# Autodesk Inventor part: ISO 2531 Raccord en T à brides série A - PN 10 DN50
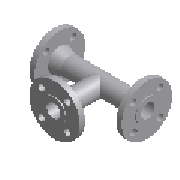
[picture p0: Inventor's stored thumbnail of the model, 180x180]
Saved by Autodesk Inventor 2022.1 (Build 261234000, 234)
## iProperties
Created: 2021-02
Part Number: ISO 2531 Raccord en T à brides série A - PN 10 DN50
Material: Fonte, ductile
Description: Tuyaux en fer malléable, raccords,accessoires et liaisons pour eau et gaz - Raccord en T à brides série A - PN 10
Document SubType Name: Modeling
Standard: ISO 2531
Designer: Fabian
Standard Revision: Fifth edition 1998-08-15
Standards Organization: ISO
Language: fr-FR
Size Designation: DN50
Categories: <MemberInstance><Categories><Category DisplayName="Tubes et tuyaux" InternalName="4347fa0f-2144-441d-94cd-e3e15c92b736" Mnemonic="TUBEANDPIPE"><CategoryParamete
Density: 7.15 g/cm^3
Appearance: Fonte grise
NAME: PIPING: ISO 2531 All Flanged Tee Series A - PN 10
DATA: <meta><inlinegroups number="1" deflen="28"></inlinegroups><connections number="3"></connections><angles><a>3.14159265358979</a><a>1.5707963267949</a></angles></
IsCustomPart: 0
Author: Fabian
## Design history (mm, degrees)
sketch "Sketch1"
  geometry: L1 (0, 25)-(300, 25); L2 (300, 25)-(300, 0); L3 (300, 0)-(0, 0); L4 (0, 0)-(0, 25); L5 (0, 25)-(0, 42); L6 (0, 42)-(3, 42); L7 (3, 42)-(3, 82.5); L8 (3, 82.5)-(19, 82.5); L9 (19, 82.5)-(19, 42); L10 (56.321, 32)-(243.679, 32); L11 (150, 0)-(150, 32); L12 (281, 82.5)-(281, 42); L13 (297, 82.5)-(281, 82.5); L14 (297, 42)-(297, 82.5); L15 (300, 42)-(297, 42); L16 (300, 25)-(300, 42); L17 (19, 42)-(56.321, 32); L18 (19, 42)-(1.5, 42); L19 (281, 42)-(243.679, 32); L20 (19, 42)-(281, 42); 1 further point
  constraints: 40 end point, 6 parallel, 4 symmetric about line, 3 midpoint, 3 perpendicular, 2 collinear, 2 horizontal, 1 coincident, 5 other
  dimensions: "d0" = 50 diameter of L1 L3 (= ID); "d1" = 7 distance between parallel lines of L1 L10 (= e1); "d2" = 84 diameter of L6 L3 (= N3); "d3" = 165 diameter of L8 L3 (= D); "d4" = 3 distance of L5.end L6.end; "d5" = 19 distance between parallel lines of L9 L5 (= C7); "d6" = 150 distance between parallel lines of L2 L11 (= 0.5 x L); "d24" = 15 deg angle of L10 L17; "d25" = 15 deg angle of L10 L19
revolve "Revolution1" sketch "Sketch1" stored, may be unused: angle "d7" = 90 deg
workplane "Work Plane1"
sketch "Sketch2"
  geometry: L1 (300, 0)-(0, 0) reference; L2 (150, 0)-(150, 32) reference; C1 r 32 at (150, 0); C2 r 25 at (150, 0)
  constraints: 2 centre point, 2 coincident, 1 concentric
  dimensions: "d9" = 50 diameter of C2 (= ID2); "d10" = 64 diameter of C1 (= ID2 + 2 x e2)
extrude "Extrusion1" join sketch "Sketch2" stored distance "d11" = 25.4; taper "d12" = 0 deg
extrude "Extrusion2" cut sketch "Sketch2" stored distance "d13" = 25.4; taper "d14" = 0 deg
sketch "Sketch3"
  geometry: L1 (-125, 131)-(-67.5, 131); L2 (-67.5, 131)-(-67.5, 147); L3 (-67.5, 147)-(-108, 147); L4 (-108, 147)-(-108, 150); L5 (-108, 150)-(-125, 150); L6 (-125, 150)-(-125, 131); L7 (-125, 131)-(-150, 131); L8 (-150, 131)-(-150, 150); L9 (-150, 150)-(-125, 150); L10 (-175, 150)-(-125, 150) reference; 1 further point
  constraints: 18 end point, 5 parallel, 3 perpendicular, 1 coincident, 1 horizontal
  dimensions: "d15" = 84 diameter of L4 L8 (= N32); "d16" = 3 distance between parallel lines of L3 L5; "d17" = 19 distance between parallel lines of L1 L5 (= C72); "d18" = 165 diameter of L2 L8 (= D2)
revolve "Revolution2" sketch "Sketch3" stored, may be unused: angle "d20" = 90 deg
sketch "Sketch7"
  geometry: L1 (44.194, 44.194)-(0, 0); L2 (0, 0)-(0, 62.5); C1 r 42 at (0, 0) reference; C2 r 9.5 at (44.194, 44.194); A1 r 62.5 centre (0, 0) between (44.194, 44.194) and (0, 62.5)
  constraints: 4 end point, 2 centre point, 2 point on circle, 1 coincident, 1 vertical
  dimensions: "d36" = 45 deg angle of L1 L2 (computed from NU); "d37" = 19 diameter of C2 (= L2); "d39" = 125 diameter of A1 (= K1)
extrude "Extrusion4" cut sketch "Sketch7" taper "d40" = 0 deg; stored distance "d46" = 10
pattern_circular "Circular Pattern1" dims angle "d21" = 360 deg
sketch "Sketch5"
  geometry: L1 (-232.5, 131)-(-67.5, 131) reference; L2 (-182, 131)-(-182, 32) reference; L3 (-118, 131)-(-118, 32) reference; L4 (-182, 131)-(-192, 131); L5 (-192, 131)-(-182, 93.679); L6 (-182, 93.679)-(-182, 131); L7 (-150, 131)-(-150, 32); L8 (-182, 32)-(-118, 32); L9 (-118, 131)-(-108, 131); L10 (-108, 131)-(-118, 93.679); L11 (-118, 93.679)-(-118, 131)
  constraints: 16 end point, 3 perpendicular, 3 symmetric about line, 2 collinear, 2 midpoint, 1 parallel, 3 other
  dimensions: "d27" = 84 diameter of L4.end L7 (= N32); "d28" = 15 deg angle of L2 L5
revolve "Revolution4" sketch "Sketch5" stored, may be unused: angle "d35" = 90 deg
sketch "Sketch6"
  geometry: L1 (44.194, -44.194)-(-44.194, 44.194); L2 (0, 0)-(62.5, 0); C1 r 82.5 at (0, 0) reference; C2 r 42 at (0, 0) reference; C3 r 9.5 at (44.194, -44.194); A1 r 62.5 centre (0, 0) between (44.194, -44.194) and (-44.194, 44.194)
  constraints: 4 end point, 3 point on circle, 2 centre point, 2 coincident, 1 concentric, 1 horizontal, 1 midpoint
  dimensions: "d30" = 125 diameter of A1 (= K12); "d31" = 19 diameter of C3 (= L22); "d42" = 45 deg angle of L2 L1 (computed from NU2)
extrude "Extrusion3" cut sketch "Sketch6" taper "d32" = 0 deg; stored distance "d38" = 10
pattern_circular "Circular Pattern3" dims angle "d34" = 360 deg
sketch "Sketch8"
  geometry: L1 (0, 0)-(0, 62.5); L2 (0, 0)-(44.194, 44.194); C1 r 42 at (0, 0) reference; C2 r 9.5 at (44.194, 44.194); A1 r 62.5 centre (0, 0) between (0, 62.5) and (44.194, 44.194); 1 further point
  constraints: 4 end point, 2 centre point, 2 coincident, 2 point on circle, 1 vertical
  dimensions: "d49" = 125 diameter of A1 (= K1); "d50" = 45 deg angle of L2 L1 (computed from NU); "d51" = 19 diameter of C2 (= L2)
extrude "Extrusion5" cut sketch "Sketch8" stored distance "d52" = 10; taper "d53" = 0 deg
pattern_circular "Circular Pattern4" dims angle "d55" = 360 deg
workaxis "Work Axis5"
workpoint "Work Point4"
workaxis "Work Axis6"
workpoint "Work Point5"
workaxis "Work Axis7"
workpoint "Work Point6"
body "Solid1"
other parameters: "D" = 165 [user parameter; used in 1 equation term], "C7" = 19 [user parameter; used in 1 equation term], "e1" = 7 [user parameter; used in 1 equation term], "ID" = 50 [user parameter; used in 1 equation term], "N3" = 84 [user parameter; used in 1 equation term], "K1" = 125 [user parameter; used in 2 equation terms], "L2" = 19 [user parameter; used in 2 equation terms], "D2" = 165 [user parameter; used in 1 equation term], "C72" = 19 [user parameter; used in 1 equation term], "ID2" = 50 [user parameter; used in 2 equation terms], "N32" = 84 [user parameter; used in 2 equation terms], "e2" = 7 [user parameter; used in 1 equation term], "K12" = 125 [user parameter; used in 1 equation term], "L22" = 19 [user parameter; used in 1 equation term], "Size_Designation" = 12.345 [user parameter]
